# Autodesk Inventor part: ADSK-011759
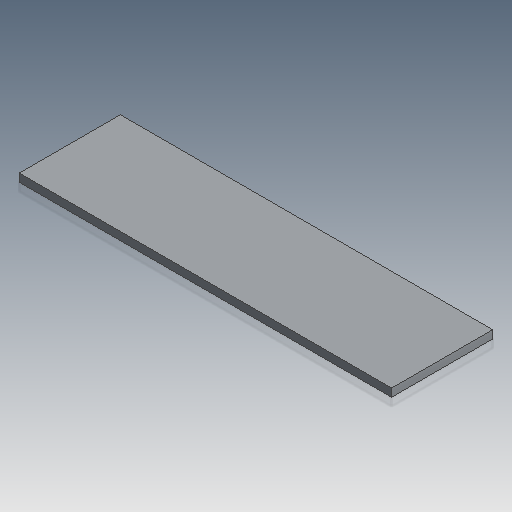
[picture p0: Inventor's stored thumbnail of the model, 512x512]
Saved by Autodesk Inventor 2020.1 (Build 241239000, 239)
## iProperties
Created: 1999-12
Part Number: ADSK-011759
Description: BELT,H150UC, 0.5P, 5.5 LONG
Document SubType Name: Modeling
Designer: sspink
Material: Générique
Density: 1 g/cm^3
Appearance: Timing Belt
Mass: 15.96 g
Surface Area: 117.08 cm^2
Volume: 15.96 cm^3
Control State: 0
Master: False
Checked Out: False
Shininess: 0.0
Length Units: 11269
Angle Units: 11279
Time Units: 11290
Mass Units: 11283
Length Display Precision: 3
Angle Display Precision: 2
Compacted: True
Dimensions: 140x3x38 mm
Mass: 0,016 kg
DocNumber: ADSK-011759.ipt
Folder: 01 - Themengebiete\Simplification\01 - Packaging machine\
VDS_Category: 3D Komponenten
Density: 0.0
Volumn: 0.0
Area: 0.0
PropertySet Name: Model Information
Author: sspink
Revision Number: -
Title: BELT,H150UC, 0.5P, 5.5 LONG
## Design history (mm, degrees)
node "Solide1"
  node "Extrusion1" dims "d5" = 38, "d6" = 0
sketch "Sketch1"
  geometry: L1 (-70, -1.5)-(70, -1.5); L2 (70, -1.5)-(70, 1.5); L3 (70, 1.5)-(-70, 1.5); L4 (-70, 1.5)-(-70, -1.5); L5 (-70, -1.5)-(70, 1.5); L6 (70, -1.5)-(-70, 1.5); 1 further point
  constraints: 12 end point, 2 midpoint, 2 parallel, 1 horizontal, 1 perpendicular
  dimensions: "d9" = 140 distance of L3.end L2.end; "d10" = 3 distance of L2.end L1.end
node "Corps solides"
node "Corps surfaciques"
